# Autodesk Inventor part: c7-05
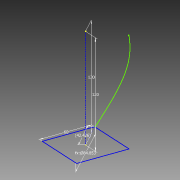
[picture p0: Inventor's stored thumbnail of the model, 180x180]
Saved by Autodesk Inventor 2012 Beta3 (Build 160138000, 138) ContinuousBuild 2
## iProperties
Created: 2010-12
Part Number: c7-05
Material: Default
Document SubType Name: Modeling
Designer: Beta-8540w
Density: 1 g/cm^3
Author: Beta-8540w
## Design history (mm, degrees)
sketch "Sketch1"
  geometry: L1 (30, 30)-(30, -30); L2 (30, -30)-(-30, -30); L3 (-30, -30)-(-30, 30); L4 (-30, 30)-(30, 30); L5 (0, 0)-(30, 30); 1 further point
  constraints: 10 end point, 1 coincident, 1 horizontal, 9 other
  dimensions: "d1" = 60 distance of L3.end L1.start; "d2" = 42.42641 distance of L5.start L1.start (derived)
sketch "Sketch2"
  geometry: L1 (0, 0)-(0, 120)
  constraints: 2 end point, 1 vertical
  dimensions: "d3" = 120 distance of L1.start L1.end
sketch "3D Sketch1"
  node "Helical Curve1" dims "d4" = 120, "d5" = 2.5, "d6" = 84.85281 (= 2 x d2), "d7" = 0
